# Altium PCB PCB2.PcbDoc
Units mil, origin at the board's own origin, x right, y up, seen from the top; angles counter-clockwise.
Board outline 3150 x 2559.06 mil, 2 copper layers (Top Layer, Bottom Layer); 69 components, 58 nets, 220 pads, 25 vias.
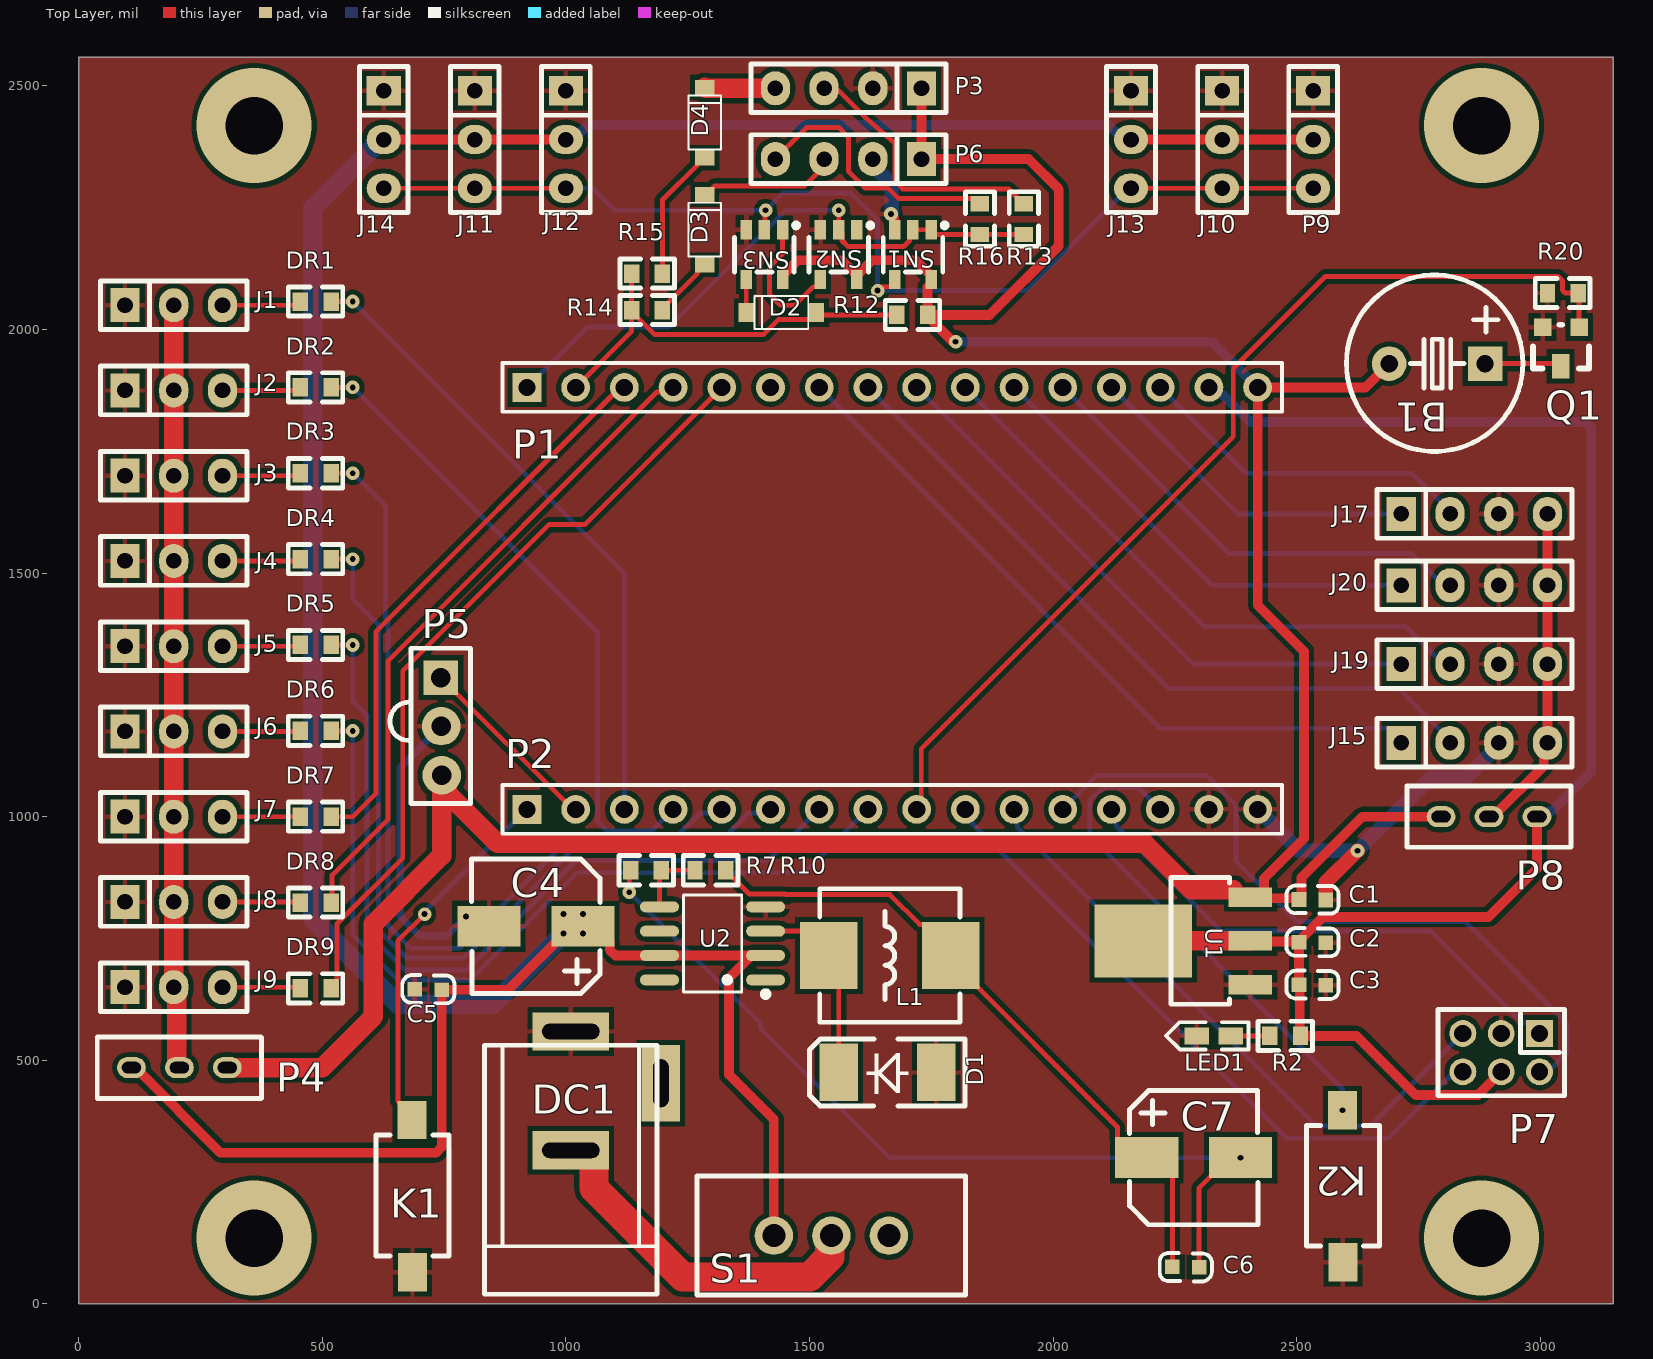
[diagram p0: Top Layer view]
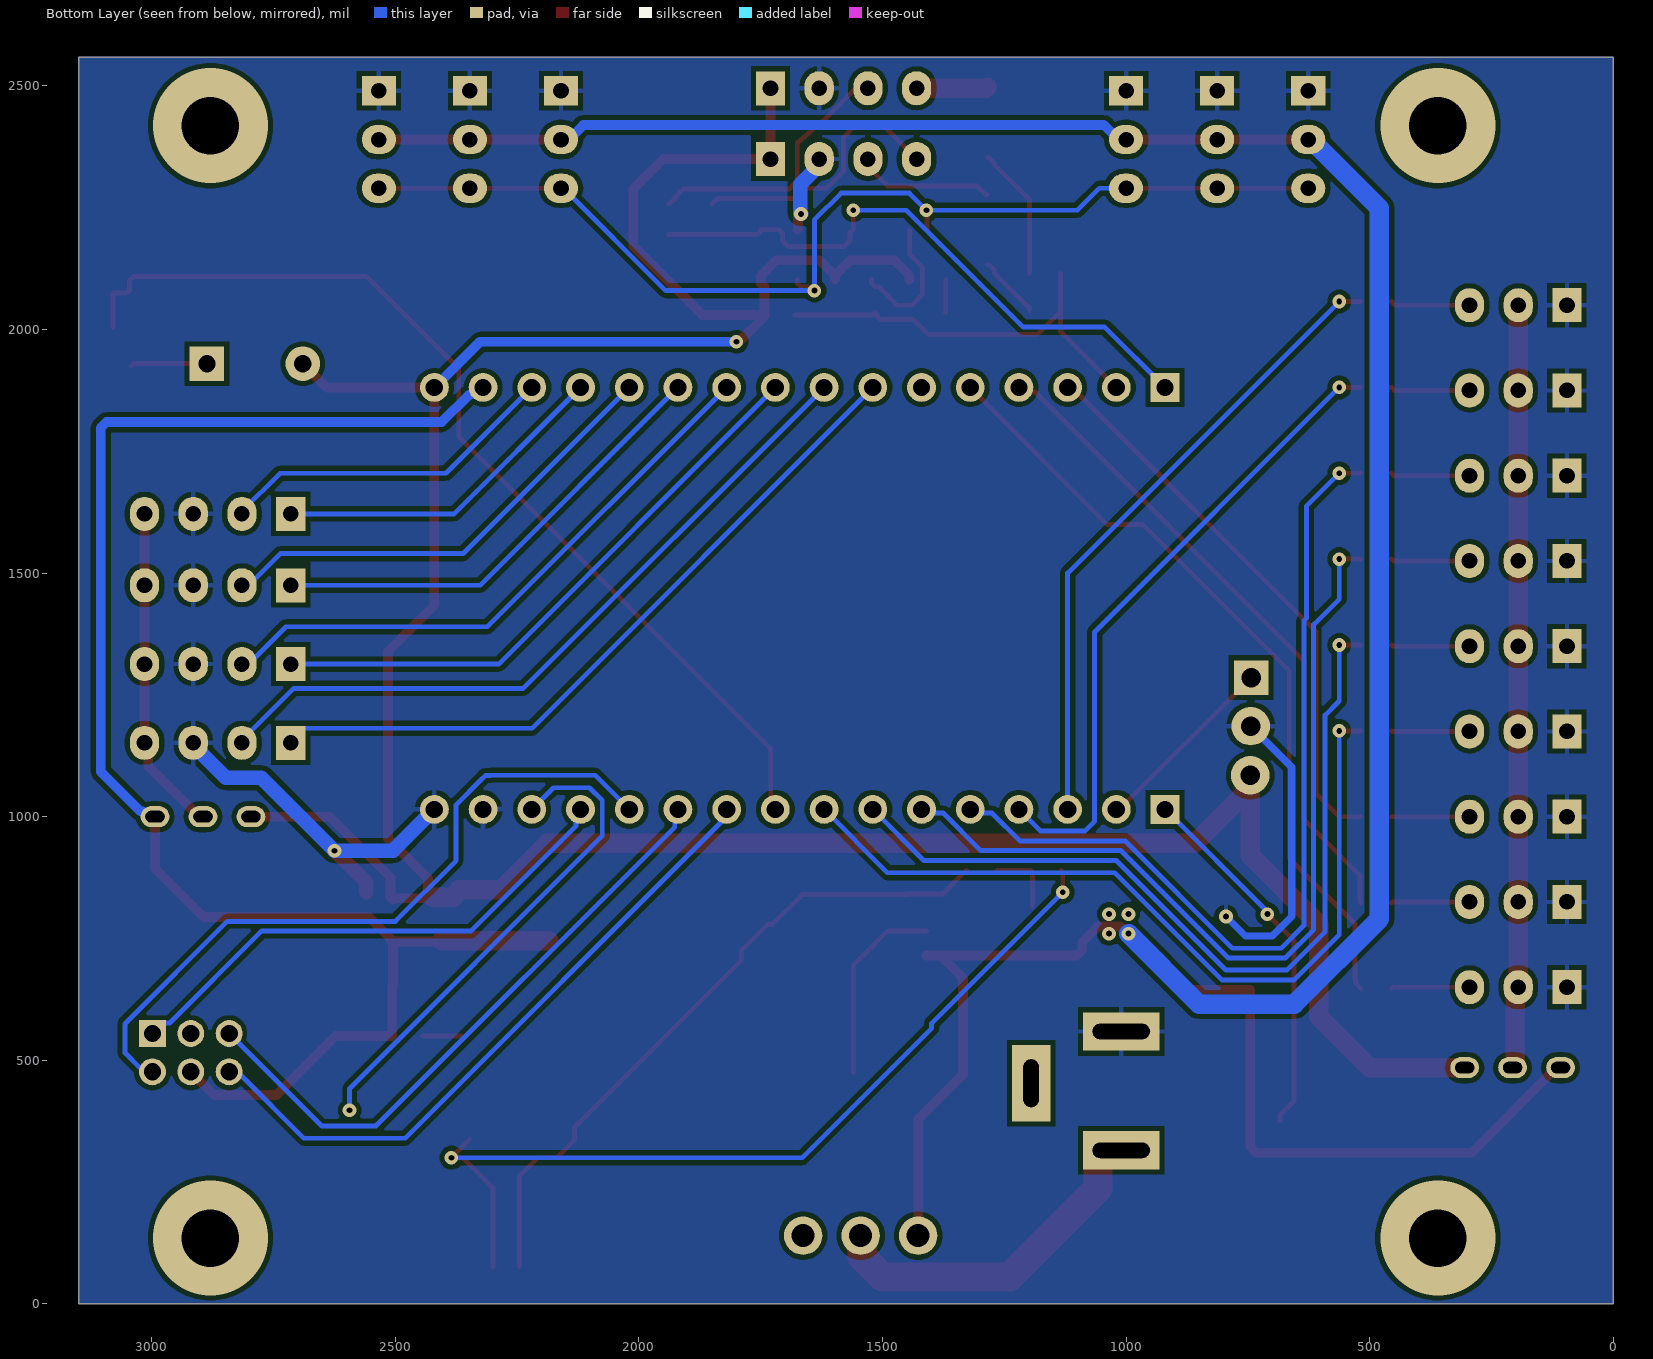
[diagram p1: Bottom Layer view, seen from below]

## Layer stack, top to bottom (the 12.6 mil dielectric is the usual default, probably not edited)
Top Solder: solder mask 0.4, Solder Resist, Dk 3.5
Top Layer: signal copper 1.4
Dielectric 1: dielectric 12.6, FR-4, Dk 4.8
Bottom Layer: signal copper 1.4
Bottom Solder: solder mask 0.4, Solder Resist, Dk 3.5

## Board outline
0,0 0,2559.05 3150,2559.06 3150,0

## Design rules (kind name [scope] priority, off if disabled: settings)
Clearance [All] p1: gap=10 ignorepadtopadclearanceinfootprint=FALSE except(0: Arc-Hole Track-Hole SMDPad-Hole THPad-Hole Via-Hole Fill-Hole Poly-Hole Region-Hole Text-Hole)
PolygonConnect [All] p1: connectstyle=Relief reliefconductorwidth=10 reliefentries=4 polygonreliefangle="90 Angle" airgapwidth=10
RoutingVias [All] p1: holewidth=28 width=50 viastyle="Through Hole" minholewidth=28 minwidth=50 maxholewidth=28 maxwidth=50
SolderMaskExpansion [All] p1: expansion=4 istentingtop=FALSE
Width [InNetClass('PWR')] p1: maxlimit=20 minlimit=20 preferedwidth=20
30 further rules are at their usual default settings.

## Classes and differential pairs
net class PWR: 3.3V 5V PWR VBAT VCC_SENSOR VCC_SERVOR

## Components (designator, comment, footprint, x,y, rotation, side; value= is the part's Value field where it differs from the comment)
B1 "BEEP" "BEEP 5x9x5.5" 2886.85,1930 r180 top
C1 "104" 0603C 2560.21,828.65 r180 top
C2 "104" 0603C 2560.21,741.15 r180 top
C3 "104" 0603C 2560.21,653.65 r180 top
C4 "220uf" SMD-EC6.3X6.3X10 1035.82,775.02 r180 top
C5 "104" 0603C 745.21,644.65 r180 top
C6 "104" 0603C 2244.79,76.35 r0 top
C7 "220uf" SMD-EC6.3X6.3X10 2191.27,299.98 r0 top
D1 "SS34" SMA/DO-214AC 1755,475 r180 top
D2 "B5819W" SOD-123 1512.5,2035 r180 top
D3 "B5819W" SOD-123 1285,2135 r90 top
D4 "B5819W" SOD-123 1285,2355 r90 top
DC1 "DC_Socket" DC-005 1010,559.09 r270 top
DR1 "1K" 0603R 455,2057.5 r0 top
DR2 "1K" 0603R 455,1881.25 r0 top
DR3 "1K" 0603R 455,1705 r0 top
DR4 "1K" 0603R 455,1528.75 r0 top
DR5 "1K" 0603R 455,1352.5 r0 top
DR6 "1K" 0603R 455,1176.25 r0 top
DR7 "1K" 0603R 455,1000 r0 top
DR8 "1K" 0603R 455,823.75 r0 top
DR9 "1K" 0603R 455,647.5 r0 top
J1 "Pin HDR1X3" "Pin HDR1X3/2.54mm-S" 95,2050 r90 top
J2 "Pin HDR1X3" "Pin HDR1X3/2.54mm-S" 95,1875 r90 top
J3 "Pin HDR1X3" "Pin HDR1X3/2.54mm-S" 95,1700 r90 top
J4 "Pin HDR1X3" "Pin HDR1X3/2.54mm-S" 95,1525 r90 top
J5 "Pin HDR1X3" "Pin HDR1X3/2.54mm-S" 95,1350 r90 top
J6 "Pin HDR1X3" "Pin HDR1X3/2.54mm-S" 95,1175 r90 top
J7 "Pin HDR1X3" "Pin HDR1X3/2.54mm-S" 95,1000 r90 top
J8 "Pin HDR1X3" "Pin HDR1X3/2.54mm-S" 95,825 r90 top
J9 "Pin HDR1X3" "Pin HDR1X3/2.54mm-S" 95,650 r90 top
J10 "Pin HDR1X3" "Pin HDR1X3/2.54mm-S" 2347,2490 r0 top
J11 "Pin HDR1X3" "Pin HDR1X3/2.54mm-S" 813,2490 r0 top
J12 "Pin HDR1X3" "Pin HDR1X3/2.54mm-S" 1000,2490 r0 top
J13 "Pin HDR1X3" "Pin HDR1X3/2.54mm-S" 2160,2490 r0 top
J14 "Pin HDR1X3" "Pin HDR1X3/2.54mm-S" 626,2490 r0 top
J15 "Pin HDR1X4" "Pin HDR1X4/2.54mm-S" 2715,1151.67 r90 top
J17 "Pin HDR1X4" "Pin HDR1X4/2.54mm-S" 2715,1621.67 r90 top
J19 "Pin HDR1X4" "Pin HDR1X4/2.54mm-S" 2715,1313.33 r90 top
J20 "Pin HDR1X4" "Pin HDR1X4/2.54mm-S" 2715,1475 r90 top
K1 "KEY" SMD-3X6X2.5 685,375 r270 top
K2 "KEY" SMD-3X6X2.5 2595,395 r270 top
L1 "INDUCTOR" 0630L 1545,715 r0 top
LED1 "LED" LED-0603Y 2365,550 r180 top
P1 "Pin HDR1X16" "Pin HDR1X16/2.54mm-S" 920,1881.14 r0 top
P2 "Pin HDR1X16" "Pin HDR1X16/2.54mm-S" 920,1015 r0 top
P3 "Pin HDR1X4" "Pin HDR1X4/2.54mm-S" 1730,2495.24 r270 top
P4 "小开关" 小开关 305,461.38 r180 top
P5 "红外" 红外接收模块 743.4,1285.6 r270 top
P6 "Pin HDR1X4" "Pin HDR1X4/2.54mm-S" 1730,2350 r270 top
P7 "2X3" "2X3P PH2.0" 2998.74,555 r180 top
P8 "小开关" 小开关 2796.59,1023.62 r0 top
P9 "Pin HDR1X3" "Pin HDR1X3/2.54mm-S" 2534,2490 r0 top
Q1 "S9013 NPN" SOT-23 3045,1970 r180 top
R2 "1K" 0603R 2507.99,550 r180 top
R7 "2K" 0603R 1195.98,890 r180 top
R10 "6.2K" 0603R 1327.99,890 r180 top
R12 "10K" 0603R 1742.5,2030 r180 top
R13 "100R" 0603R 1940,2257.99 r270 top
R14 "100R" 0603R 1197.99,2040 r180 top
R15 "100R" 0603R 1197.99,2115 r180 top
R16 "100R" 0603R 1850,2257.99 r270 top
R20 "10K" 0603R 3015,2075 r0 top
S1 "SS-12D10" SS-12D10 1663.11,140 r180 top
SN1 "Component_1" SN74HC 1749.9,2102.63 r90 top
SN2 "Component_1" SN74HC 1597.4,2102.63 r90 top
SN3 "Component_1" SN74HC 1444.9,2102.63 r90 top
U1 "AMS1117" SOT223 2405,745 r90 top
U2 "TD1583(5V3A)" TD1583 1410,665 r90 top

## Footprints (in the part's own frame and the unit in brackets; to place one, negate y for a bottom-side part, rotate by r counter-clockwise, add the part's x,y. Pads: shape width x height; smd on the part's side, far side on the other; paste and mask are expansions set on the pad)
"2X3P PH2.0" [mm]
  rect 1.4x1.4 hole 0.9 mask+0.051: 1(0,0)
  round 1.4 hole 0.9 mask+0.051: 2(0,2) 3(2,0) 4(2,2) 5(4,0) 6(4,2)
  silkscreen extent -1.3,-1.25 5.3,3.25
0603C [mil]
  rect 30x30 smd: 1(0.21,-0.35) 2(55.21,-1.35)
  silkscreen extent -26,-30 81,28, body extent -1,-15 62,17, height 12
0603R [mm]
  rect 0.8x0.965 smd: 1(0,0) 2(1.6,0)
  silkscreen extent -0.64,-0.76 2.21,0.76, body extent -0.04,-0.41 1.56,0.41, height 0.45
0630L [mm]
  rect 3x3.5 smd: 1(-0.127,0) 2(6.223,0)
  silkscreen extent -0.61,-3.48 6.71,3.48, body extent -0.55,-3.05 6.4,3.55, height 3.05
"BEEP 5x9x5.5" [mm]
  rect 1.8x1.8 hole 0.9: 1(0,0)
  round 1.8 hole 0.9: 2(5,0)
  silkscreen extent -1.97,-4.62 7.23,4.57, body extent -1.96,-4.44 7.04,4.55, height 5.45
DC-005 [mm] "5.5X2.1mm"
  rect 2x4 hole 0.8 slot 3 at 90 deg: 1(0,0) 2(6.2,0)
  rect 4x2 hole 0.8 slot 2.5 at 0 deg: 3(2.7,4.7)
  silkscreen extent 0.72,-4.5 13.7,4.5, body extent -0.4,-4.52 13.65,4.78, height 11.2
LED-0603Y [mil]
  rect 50x35 smd: A(0,0) K(70,0)
  silkscreen extent -36,-28 133,28, body extent 4,-17 66,15, height 24
"Pin HDR1X3/2.54mm-S" [mil]
  rect 70x60 hole 32: 1(0,0)
  oval 70x60 hole 32: 2(0,-100) 3(0,-200)
  silkscreen extent -50,-250 50,50, body extent -50,-250 50,50, height 336
"Pin HDR1X4/2.54mm-S" [mil]
  rect 70x60 hole 32: 1(0,0)
  oval 70x60 hole 32: 2(0,-100) 3(0,-200) 4(0,-300)
  silkscreen extent -50,-350 50,50, body extent -50,-350 50,50, height 336
"Pin HDR1X16/2.54mm-S" [mm]
  rect 1.5x1.5 hole 0.9: 1(0,0)
  round 1.5 hole 0.9: 2(2.54,0) 3(5.08,0) 4(7.62,0) 5(10.16,0) 6(12.7,0) 7(15.24,0) 8(17.78,0) 9(20.32,0) 10(22.86,0) 11(25.4,0) 12(27.94,0) 13(30.48,0) 14(33.02,0) 15(35.56,0) 16(38.1,0)
  silkscreen extent -1.27,-1.27 39.37,1.27, body extent -1.27,-1.27 39.37,1.27, height 7.58
SMA/DO-214AC [mm] "塑封二极管"
  rect 2x3 smd: A(-0.127,0) K(4.953,0)
  silkscreen extent -1.63,-1.75 6.48,1.75, body extent 0.11,-1.35 4.71,1.35, height 2.4
SMD-3X6X2.5 [mm]
  rect 2x1.5 smd: 1(-0.059,-0.02) 3(7.874,0)
  silkscreen extent 0.73,-1.9 7.03,1.9, body extent -0.19,-1.78 7.81,1.72, height 2.59
SMD-EC6.3X6.3X10 [mm]
  rect 3.3x2.132 smd: 1(0.021,0) 2(4.921,0)
  silkscreen extent -0.88,-3.5 5.84,3.5, body extent -1.09,-3.3 5.91,3.3, height 5.4
SN74HC [mm]
  rect 1x0.6 smd mask+0.051: 1(2.6,0) 2(2.6,0.95) 3(2.6,1.9) 4(0,1.9) 5(0,0)
  silkscreen extent 0.4,-0.83 2.95,2.5
SOD-123 [mm] "塑封二极管"
  rect 0.8x1 smd: A(-0.051,0) K(3.607,0)
  silkscreen extent 0.38,-0.85 3.18,0.85, body extent -0.12,-0.89 3.73,0.81, height 1.43
SOT223 [mil]
  rect 40x90 smd: 1(-90,0) 2(0,0) 3(90,0)
  rect 150x200 smd: 2(0,220)
  silkscreen extent -130,43 130,163, body extent -130,-30 126,246, height 65
SOT-23 [mil]
  rect 36x36 smd: B(-35,-35) E(40,-35)
  rect 36x50 smd: C(3,45)
  silkscreen extent -55,-40 60,50, body extent -54,-48 60,62, height 47
SS-12D10 [mm]
  round 2 hole 1.2: 1(0,0) 2(3,0) 3(6,0)
  silkscreen extent -4,-3.1 10,3.1, body extent -3.95,-3.15 10.05,3.05, height 9.65
TD1583 [mil]
  oval 22.6x80.14 smd mask+2: 1(0,0) 2(50,0) 3(100,0) 4(150,0) 5(150,217.94) 6(100,217.94) 7(50,217.94) 8(0,217.94)
  silkscreen extent -35,-6 174,169
小开关 [mm]
  oval 1.5x1.1 hole 0.6 slot 1 at 0 deg mask+0.05: 1(0,-0.6) 2(2.5,-0.6) 3(5,-0.6)
  silkscreen extent -1.78,-2.19 6.78,1.01
红外接收模块 [mil]
  rect 71x71 hole 40 mask+2: 1(0,0)
  round 79 hole 40 mask+2: 2(99.7,0.7) 3(200.6,1.6)
  silkscreen extent -60,-105 259,61

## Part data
B1: "蜂鸣器"
C1 C2 C3 C5 C6: library part CAP, "无极性电容"
C4 C7: library part SMD_ECAP, "贴片电解电容"
D1 D2 D3 D4: library part "DIODE SCHOTTKY", "肖特基二极管"
DR1 DR2 DR3 DR4 DR5 DR6 DR7 DR8 DR9 R2 R7 R10 R12 R13 R14 R15 R16 R20: library part RES
P7: library part "2X3 PH3.0"
Q1: library part NPN, "NPN三极管"
U1: "三端稳压芯片"

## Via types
v1: diameter 28, hole 12, Top Layer to Bottom Layer, tented both sides, 21 vias
v2: diameter 236.22, hole 118.11, Top Layer to Bottom Layer, 4 vias

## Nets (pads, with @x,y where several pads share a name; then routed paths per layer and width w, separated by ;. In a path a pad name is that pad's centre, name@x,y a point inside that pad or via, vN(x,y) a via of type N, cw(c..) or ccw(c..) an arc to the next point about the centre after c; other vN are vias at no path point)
3.3V: C2.2 C3.2 P1.15 P7.4 P8.3 R2.1 U1.2 | length 3330.4
  Top Layer w20: U1.2@2405,745 2406.25,743.75 2503.75,743.75 C2.2 ; P7.4 2872.44,428.7 2744.49,428.7 2623.19,550 R2.1 2506.5,551.5 2506.5,653.5 C3.2 C2.2 ; P8.3 2993.43,893.43 2894,794 2554.22,794 2510,749.78 2510,747.5 C2.2
  Top Layer w40: U1.2@2185,745 U1.2@2405,745
  Bottom Layer w20: P1.15 2330.57,1881.14 2345.73,1865.98 2349.02,1865.98 2405,1810 3093.28,1810 3105,1798.28 3105,1092.78 3023.28,1011.07 3018.69,1011.07 3007.62,1000 P8.3
5V: B1.2 C1.2 P1.16 P3.1 P4.1 P5.3 P6.1 P8.1 R12.1 SN1.5 SN2.5 SN3.5 U1.3 | length 6629.9
  Top Layer w20: SN3.5 1444.9,2110.5 1476.71,2142.31 1565.59,2142.31 SN2.5@1597.4,2110.5 ; SN2.5 SN2.5@1597.4,2110.5 ; P3.1 P6.1 1950,2350 2011.72,2288.28 2011.72,2171.72 1870,2030 R12.1 ; v1(1800,1975) 1794.25,1975 1742.5,2026.75 R12.1 ; U1.3@2370,850 2370,845 U1.3@2380,835 ; U1.3@2423.28,835 2433.28,845 2433.28,873.28 2515,955 2515,1339.54 2420,1434.54 P1.16 2641.14,1881.14 B1.2 ; U1.3@2430,832.5 2502.5,832.5 C1.2 2510,835 2510,875 2635,1000 P8.1 ; SN2.5@1597.4,2110.5 1629.21,2142.31 1718.09,2142.31 1749.9,2110.5 SN1.5 1749.9,2094.76 1742.5,2087.36 R12.1
  Top Layer w40: P4.1 500,485 605,590 605,780 745,920 P5.3@745,1048.71 ; P5.3 756.29,1073.71 756.29,1048.71 860,945 2188.28,945 2283.28,850 U1.3@2370,850 ; U1.3@2380,835 U1.3@2423.28,835
  Bottom Layer w20: v1(1800,1975) 2326.14,1975 P1.16
BEEP: P2.9 Q1.B R20.2 | length 2056.8
  Top Layer w10: P2.9 1729.39,1024.39 1729.39,1139.39 2370,1780 2370,1920 2559,2109 3036.96,2109 3045.75,2100.21 3045.75,2080.86 3051.61,2075 R20.2 3080,2072.99 Q1.B
DAT: J10.3 J11.3 J12.3 J13.3 J14.3 P9.3 SN1.4 SN3.2 | length 2286
  Top Layer w10: J14.3 J11.3 J12.3 ; SN3.2 1408.75,2206.25 1408.75,2243.75 v1(1410,2245) ; v1(1640,2080) 1647.95,2087.94 1668.29,2087.94 1675.1,2094.76 SN1.4 ; J13.3 J10.3 P9.3
  Bottom Layer w10: J12.3 1055,2290 1100,2245 v1(1410,2245) 1445,2280 1585,2280 1640,2225 v1(1640,2080) 1945,2080 2155,2290 J13.3
DJ0: DR1.2 P2.3 | length 1317.9
  Top Layer w10: DR1.2 v1(562.5,2057.5)
  Bottom Layer w10: v1(562.5,2057.5) 1120,1500 P2.3
DJ1: DR2.2 P2.4 | length 1325.4
  Top Layer w10: DR2.2 v1(562.5,1881.25)
  Bottom Layer w10: v1(562.5,1881.25) 1064.53,1379.22 1064.53,990.47 1084.53,970.47 1175.47,970.47 P2.4
DJ2: DR3.2 P2.5 | length 1825.3
  Top Layer w10: DR3.2 v1(562.5,1705)
  Bottom Layer w10: v1(562.5,1705) 630,1637.5 630,1407.47 635,1402.47 635,776.57 681.57,730 781.72,730 1002.19,950.47 1218.44,950.47 1275.47,1007.5 1312.5,1007.5 P2.5
DJ3: DR4.2 P2.6 | length 1782.2
  Top Layer w10: DR4.2 v1(562.5,1528.75)
  Bottom Layer w10: v1(562.5,1528.75) 562.5,1446.68 615,1394.18 615,768.28 673.28,710 790,710 1010.47,930.47 1298.44,930.47 1375.47,1007.5 1412.5,1007.5 P2.6
DJ4: DR5.2 P2.7 | length 1743.2
  Top Layer w10: DR5.2 v1(562.5,1352.5)
  Bottom Layer w10: v1(562.5,1352.5) 562.5,1237.5 591.5,1208.5 591.5,763.5 670,685 795,685 1020,910 1415,910 P2.7
DJ5: DR6.2 P2.8 | length 1704
  Top Layer w10: DR6.2 v1(562.5,1176.25)
  Bottom Layer w10: v1(562.5,1176.25) 562.5,757.5 655,665 803.28,665 1023.28,885 1490,885 P2.8
DJ6: DR7.2 P1.3 | length 1161.8
  Top Layer w10: DR7.2 562.5,1000 610,1047.5 610,1380 1111.14,1881.14 P1.3
DJ7: DR8.2 P1.4 | length 1362.1
  Top Layer w10: DR8.2 520,825.76 520,880 635,995 635,1320 1186.76,1871.76 1210.61,1871.76 P1.4
DJ8: DR9.2 P1.5 | length 1608.8
  Top Layer w10: DR9.2 528.74,658.25 528.74,666.09 530,667.35 530,779.8 665,914.8 665,1299.41 965.12,1599.53 1038.39,1599.53 P1.5
GND: C1.1 C2.1 C3.1 C4.2 C5.2 D1.A DC1.1 J1.1 J2.1 J3.1 J4.1 J5.1 J6.1 J7.1 J8.1 J9.1 J10.1 J11.1 J12.1 J13.1 J14.1 J15.3 J17.3 J19.3 J20.3 K1.3 K2.3 LED1.K P2.15 P2.16 P3.2 P5.2 P6.2 P7.3 P9.1 Q1.E R20.1 SN1.3 SN2.3 SN3.3 U1.1 U2.4 | length 1495.6
  Top Layer w20: v1(1667.34,2237.34) 1667.34,2235.18 1673.29,2229.23 1673.29,2206.81 SN1.3
  Top Layer w30: 2560,845 2560,865 v1(2625,930)
  Bottom Layer w10: P6.2@1630,2345 P6.2
  Bottom Layer w15: P5.2 660,1101.8 660,795 700,755 755,755 v1(795,795)
  Bottom Layer w30: P6.2@1630,2345 1630,2336.88 1668.71,2298.17 1668.71,2238.71 v1(1667.34,2237.34) ; P2.16 2505,930 v1(2625,930) 2775,1080 2848.33,1080 2915,1146.67 J15.3
IR: P2.2 P5.1 | length 388.7
  Top Layer w10: P5.1 1014,1015 P2.2
KEY1: K1.1 P2.1 | length 759.6
  Top Layer w10: K1.1 684.21,387.16 655,416.37 655,745 v1(710,800)
  Bottom Layer w10: v1(710,800) 713.44,803.44 713.44,808.44 P2.1
KEY2: K2.1 P2.14 | length 1024.8
  Bottom Layer w10: P2.14 2175.47,1059.53 2101.56,1059.53 2075.47,1033.44 2075.47,960.46 2594.21,441.72 v1(2594.21,397.31)
NetB1_1: B1.1 Q1.C | length 157.2
  Top Layer w10: B1.1 3037,1930 Q1.C
NetC6_1: C6.1 C7.1 L1.2 R10.1 | length 1390.5
  Top Layer w10: R10.1 1376.69,841.3 1449.66,841.3 1450.96,840 1665,840 1726.1,778.9 1735.94,778.9 1790,724.84 L1.2 1790,705.16 2132.13,363.03 2132.13,336.97 2169.09,300 C7.1 2208.03,300 2245,263.03 C6.1
NetC6_2: C6.2 C7.2 R7.2 | length 1858.8
  Top Layer w10: v1(1130,845) 1130,887.01 R7.2 ; C6.2 2300,237.99 2362.01,300 v1(2385,300) C7.2@2348.03,336.97
  Bottom Layer w10: v1(1130,845) 1399.22,575.78 1399.22,565.78 1665,300 v1(2385,300)
NetD1_K: D1.K L1.1 U2.3 | length 399
  Top Layer w10: U2.3 1490,765 L1.1 1560,695 D1.K
NetD2_K: D2.K SN3.4 | length 67.8
  Top Layer w10: SN3.4 1370.1,2035.4 D2.K
NetD3_A: D3.A R14.1 | length 131.3
  Top Layer w10: R14.1 1197.99,2043.25 1270.32,2115.57 1270.32,2122.25 1281.06,2133 D3.A
NetD3_K: D3.K P6.3 | length 284.8
  Top Layer w10: D3.K 1288.94,2277 1299.69,2287.75 1299.69,2289.14 1305.54,2295 1490,2295 1530,2335 P6.3
NetD4_A: D4.A R15.1 | length 276.3
  Top Layer w10: R15.1 1197.99,2265.99 1270.32,2338.31 1270.32,2342.25 1281.06,2353 D4.A
NetD4_K: D4.K P3.4 | length 145.7
  Top Layer w40: D4.K 1286.76,2495.24 P3.4
NetDR1_1: DR1.1 J1.3 | length 163.1
  Top Layer w10: J1.3 447.5,2050 DR1.1
NetDR2_1: DR2.1 J2.3 | length 162.6
  Top Layer w10: J2.3 448.75,1875 DR2.1
NetDR3_1: DR3.1 J3.3 | length 162.1
  Top Layer w10: J3.3 450,1700 DR3.1
NetDR4_1: DR4.1 J4.3 | length 161.6
  Top Layer w10: J4.3 451.25,1525 DR4.1
NetDR5_1: DR5.1 J5.3 | length 161
  Top Layer w10: J5.3 452.5,1350 DR5.1
NetDR6_1: DR6.1 J6.3 | length 160.5
  Top Layer w10: J6.3 453.75,1175 DR6.1
NetDR7_1: DR7.1 J7.3 | length 160
  Top Layer w10: J7.3 DR7.1
NetDR8_1: DR8.1 J8.3 | length 160.5
  Top Layer w10: J8.3 453.75,825 DR8.1
NetDR9_1: DR9.1 J9.3 | length 161
  Top Layer w10: J9.3 452.5,650 DR9.1
NetLED1_A: LED1.A R2.2 | length 80
  Top Layer w10: LED1.A R2.2
NetP3_3: P3.3 R13.1 | length 553.7
  Top Layer w10: P3.3 1550.62,2495.24 1554.76,2495.24 1615.39,2434.61 1618.29,2431.71 1675,2382.8 1675,2305 1691.26,2288.74 1909.25,2288.74 1926,2271.99 1926,2268.74 1936.75,2257.99 R13.1
NetP6_4: P6.4 R16.1 | length 553
  Top Layer w10: P6.4 1472.45,2392.45 1495,2415 1560,2415 1580,2395 1580,2325 1615,2290 1661.72,2290 1682.98,2268.74 1839.25,2268.74 R16.1
NetR7_1: R7.1 R10.2 U2.5 | length 145.6
  Top Layer w10: U2.5 1192.06,886.08 R7.1 R10.2
NetSN2_4: SN2.4 SN3.1 | length 284.2
  Top Layer w10: SN3.1 1444.9,2155.34 1418.09,2128.53 1418.09,2071.91 1440,2050 1469.97,2050 1507.91,2087.94 1515.79,2087.94 1522.6,2094.76 SN2.4
PS1: P2.13 P7.1 | length 1083.9
  Bottom Layer w10: P2.13 2128.99,1006.01 2128.99,981.01 2345,765 2775,765 2963.7,576.3 2977.44,576.3 P7.1
PS2: P2.12 P7.2 | length 1475
  Bottom Layer w10: P2.12 2090,1085 2305,1085 2305.6,1084.4 2315.6,1084.4 2323.33,1076.67 2375.47,1024.53 2375.47,909.53 2500,785 2845.07,785 3055,575.07 3055,515 3024.89,484.89 3007.37,484.89 P7.2
PS6: P2.11 P7.5 | length 1286.8
  Bottom Layer w10: P2.11 1926.49,1008.51 1926.49,978.51 2540,365 2651.26,365 P7.5
PS7: P2.10 P7.6 | length 1366.1
  Bottom Layer w10: P2.10 1820,1001.73 1833.99,987.74 1833.99,986.01 2480,340 2687.84,340 2815.47,467.63 2832.63,467.63 P7.6
PWR: DC1.2 S1.2 | length 741.6
  Top Layer w60: DC1.2 1048.32,315 1057.69,305.63 1057.69,237.31 1240,55 1500.48,55 1541.41,95.93 1541.41,136.41 S1.2
RXD1: D2.A P1.2 R12.2 R14.2 R15.2 | length 868.4
  Top Layer w10: P1.2 1135,1996.14 R14.2@1135,2036.75 ; R15.2 R14.2 R14.2@1135,2036.75 ; R12.2 1519.5,2030 D2.A 1514.5,2031.06 1503.75,2020.32 1436.15,2020.32 1405.83,1990 1181.75,1990 R14.2@1135,2036.75
SSA3: J15.1 P1.7 | length 1500.1
  Bottom Layer w10: P1.7 2219.47,1181.67 2690,1181.67 2715,1156.67 J15.1
SSA4: J19.1 P1.9 | length 1230.2
  Bottom Layer w10: P1.9 2287.81,1313.33 J19.1
SSA5: J20.1 P1.11 | length 963.2
  Bottom Layer w10: P1.11 2326.14,1475 J20.1
SSA6: J17.1 P1.13 | length 702.5
  Bottom Layer w10: P1.13 2379.47,1621.67 J17.1
SSD3: J15.2 P1.8 | length 1500.1
  Bottom Layer w10: P1.8 2237.81,1263.33 2708.33,1263.33 2815,1156.67 J15.2
SSD4: J19.2 P1.10 | length 1230.2
  Bottom Layer w10: P1.10 2311.14,1390 2724.55,1390 2786.65,1327.9 2800.43,1327.9 J19.2
SSD5: J20.2 P1.12 | length 963.2
  Bottom Layer w10: P1.12 2361.14,1540 2736.21,1540 2786.65,1489.57 2800.43,1489.57 J20.2
SSD6: J17.2 P1.14 | length 705.4
  Bottom Layer w10: P1.14 2396.14,1705 2736.67,1705 2815,1626.67 J17.2
TXD1: P1.1 R13.2 R16.2 SN1.1 SN1.2 SN2.2 | length 1263.4
  Top Layer w10: v1(1560,2245) SN2.2 1566.81,2198.19 1566.81,2182.88 1579.38,2170.31 1693.12,2170.31 1705.69,2182.88 1705.69,2198.19 SN1.2 SN1.1 1749.9,2201.81 1756.71,2195 R16.2 R13.2
  Bottom Layer w10: P1.1 1043.86,2005 1211.01,2005 1451.01,2245 v1(1560,2245)
VBAT: C4.1 C5.1 J10.2 J11.2 J12.2 J13.2 J14.2 P4.3 P9.2 S1.3 U2.2 U2.7 | length 6667.6
  Top Layer w20: P4.3 116.03,485 291.03,310 733.28,310 745,321.72 C5.1 880.01,645 881.01,644 1012.01,775 C4.1 1057.99,775 1089.96,743.03 1089.96,726.72 1101.68,715 U2.2@1381.23,715 ; J14.2 J11.2 J12.2 ; U2.2 U2.2@1381.23,715 ; S1.3 1426.89,378.45 1335,470.34 1335,668.77 U2.2@1381.23,715 ; J13.2 J10.2 P9.2
  Bottom Layer w20: J14.2@621,2390 J14.2 ; J12.2 1015.82,2390 1045.82,2420 2114.18,2420 2144.18,2390 J13.2
  Bottom Layer w40: J14.2@621,2390 480,2249 480,790 655,615 850,615 v1(995,760)
  other v1: 1035,760 995,800 1035,800
VCC_SENSOR: J15.4 J17.4 J19.4 J20.4 P8.2 | length 677.6
  Top Layer w20: P8.2@2893.43,1000 P8.2 2902.87,1000 3007.35,1104.47 3007.35,1144.01 J15.4 J19.4 J20.4 J17.4
VCC_SERVOR: J1.2 J2.2 J3.2 J4.2 J5.2 J6.2 J7.2 J8.2 J9.2 P4.2 | length 1569.8
  Top Layer w40: J1.2 J2.2 J3.2 J4.2 J5.2 J6.2 J7.2 J8.2 J9.2 200.79,644.21 200.79,490.79 P4.2
pads on no net: DC1.3 P1.6 S1.1 SN2.1 U2.1 U2.6 U2.8
copper on no net:
  other v2: 360,135 2879.69,135 360,2418.46 2879.69,2418.46

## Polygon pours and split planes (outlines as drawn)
GND on Top Layer "NONET_L-01_P-001" (solid, pour order 1): 0,0 3150,0 3150,2560 0,2560
GND on Bottom Layer "NONET_L-01_P-001" (solid, pour order 2): 0,0 0,2560 3150,2560 3150,0

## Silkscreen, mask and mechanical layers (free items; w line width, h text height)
Mechanical 1:
  lines w10: 0,0 0,2559.06 3150,2559.06 3150,0 3149.61,0 0,0

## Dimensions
0,0 to 3149.61,0 on Mechanical 1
